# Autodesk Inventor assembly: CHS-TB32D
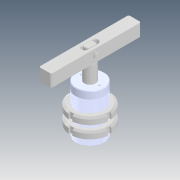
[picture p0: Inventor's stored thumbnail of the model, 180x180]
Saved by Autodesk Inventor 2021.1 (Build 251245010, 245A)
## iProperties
Created: 2020-02
Part Number: CHS-TB32D
Description: STEP AP214
Document SubType Name: Assembly
Designer: user
Title: chs-tb32d_asm.STEP
Revision Number: ÈÎºÎ
Sending System: SolidWorks 2016
Preprocessor: SwSTEP 2.0
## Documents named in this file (7)
- D:\Vault_2016\Projekty\Clamptek\Hydraulic\CHS\CHS-32\Inventor\CHS-TB32D\CHS-TB32D.iam
- D:\Vault_2016\Projekty\Clamptek\Hydraulic\CHS\CHS-32\Inventor\CHS-TB32D\CHS-TB32-03.ipt
- D:\Vault_2016\Projekty\Clamptek\Hydraulic\CHS\CHS-32\Inventor\CHS-TB32D\CHS-TB32-04.ipt
- D:\Vault_2016\Projekty\Clamptek\Hydraulic\CHS\CHS-32\Inventor\CHS-TB32D\CHS-32D-02_6.ipt
- D:\Vault_2016\Projekty\Clamptek\Hydraulic\CHS\CHS-32\Inventor\CHS-TB32D\CHS-32D-01_8.ipt
- D:\Vault_2016\Projekty\Clamptek\Hydraulic\CHS\CHS-32\Inventor\CHS-TB32D\Xiaozhou.ipt
- D:\Vault_2016\Projekty\Clamptek\Hydraulic\CHS\CHS-32\Inventor\CHS-TB32D\Öá8µ²È¦.ipt
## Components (8 placed, 8 different names)
1. CHS-TB32-03_1
2. CHS-TB32-04_2
3. CHS-TB32-04_3
4. CHS-32D-02_6_4
5. CHS-32D-01_8_5
6. Xiaozhou_6
7. Öá8µ²È¦_7
8. Öá8µ²È¦_8
